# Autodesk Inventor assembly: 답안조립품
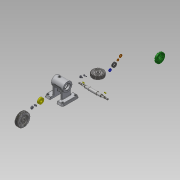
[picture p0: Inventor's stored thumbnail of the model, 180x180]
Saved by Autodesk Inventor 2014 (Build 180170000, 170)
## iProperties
Created: 2016-07
Part Number: 답안조립품
Document SubType Name: Assembly
Designer: net
Author: net
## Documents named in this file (16)
- C:\Users\net\Desktop\460707V1011\답안조립품.iam
- C:\Users\net\Desktop\460707V1011\V벨트풀리.ipt
- C:\Users\net\Desktop\460707V1011\너트 M 8.ipt
- C:\Users\net\Desktop\460707V1011\니플 M 6 x 0.75.ipt
- C:\Users\net\Desktop\460707V1011\베어링 15 x 32 x 9.ipt
- C:\Users\net\Desktop\460707V1011\본체.ipt
- C:\Users\net\Desktop\460707V1011\볼트 M 6 x 8.ipt
- C:\Users\net\Desktop\460707V1011\볼트 M4 x 12.ipt
- C:\Users\net\Desktop\460707V1011\스퍼기어.ipt
- C:\Users\net\Desktop\460707V1011\스프링와셔 8.ipt
- C:\Users\net\Desktop\460707V1011\오일 실 15 25 7.ipt
- C:\Users\net\Desktop\460707V1011\와셔 6x11.5.ipt
- C:\Users\net\Desktop\460707V1011\와셔 8x17.ipt
- C:\Users\net\Desktop\460707V1011\축.ipt
- C:\Users\net\Desktop\460707V1011\커버.ipt
- C:\Users\net\Desktop\460707V1011\키 3 x 3 x 12.ipt
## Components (3 placed, 3 different names)
1. V벨트풀리:1
2. KS B 2023 6002 - 15 x 32 x 9:1
3. ISO 4762 M4 x 12:1
